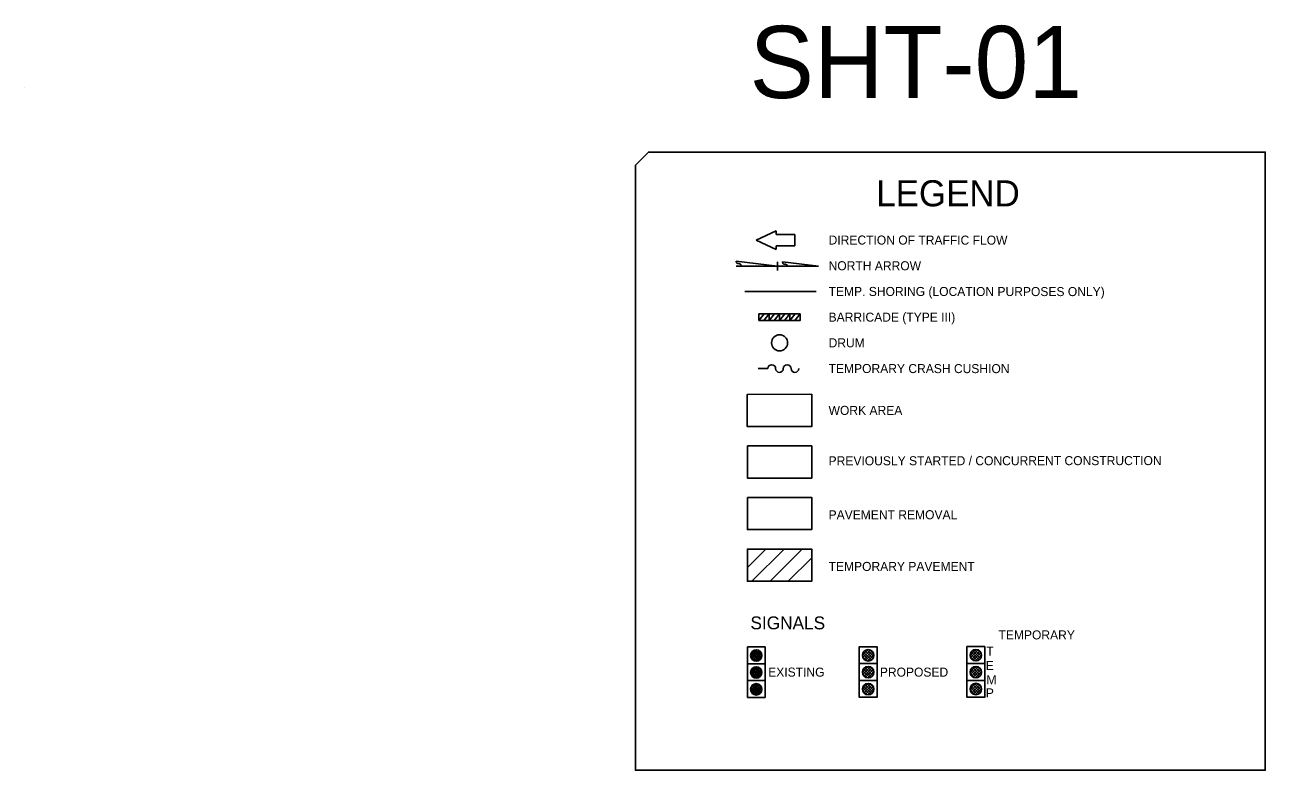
# Model space of a CAD drawing. Extents: x 2486454 to 2490507, y 369321 to 372999.
# Drawn here: x 2487512 to 2488475, y 372420 to 372999 of the extents above; entities that cross this region are included whole.
import ezdxf

# ---------------------------------------------------------------- set-up
doc = ezdxf.new("R2010")
doc.units = 0
for name, color, linetype in [('DEV BORDER CELL', 7, 'Continuous'), ('Scratch_Level_3', 7, 'Continuous'), ('TC CONSTRUCTION PROPOSED ROADWAY SHADE', 7, 'Continuous'), ('TC CONSTRUCTION REMOVAL OF EXIST ASPH PVMT HATCHING', 7, 'Continuous'), ('TC CONSTRUCTION TEMP PAVEMENT FULL DEPTH SHADE', 7, 'Continuous'), ('TC CONSTRUCTION TEMP PAVEMENT HATCHING', 7, 'Continuous'), ('TC CONSTRUCTION TEMP SHORING', 7, 'Continuous'), ('TC DEV ATTENUATOR', 7, 'Continuous'), ('TC DEV BARRICADE', 7, 'Continuous'), ('TC DEV DRUM', 7, 'Continuous'), ('TC DEV SIGNAL', 7, 'Continuous'), ('TC LABEL DIRECTION OF TRAFFIC FLOW ARROW', 7, 'Continuous'), ('TC SHEET BORDER LINE THIN', 7, 'Continuous'), ('TC SHEET LAYOUT SHAPE', 7, 'Continuous'), ('TC SHEET NORTH ARROW', 7, 'Continuous'), ('TC SHEET TEXT', 7, 'Continuous')]:
    doc.layers.add(name, color=color, linetype=linetype)

msp = doc.modelspace()

# ---------------------------------------------------------------- linework, layer by layer
at = {"layer": 'DEV BORDER CELL'}
msp.add_lwpolyline([(2488122.95, 372711.96), (2488072.95, 372711.93), (2488072.96, 372686.93), (2488122.96, 372686.96)], close=True, dxfattribs=at)
at = {"layer": 'Scratch_Level_3'}
msp.add_line((2487512.21, 372950.09), (2487512.21, 372950.09), dxfattribs=at)
at = {"layer": 'TC CONSTRUCTION PROPOSED ROADWAY SHADE'}
msp.add_lwpolyline([(2488072.95, 372711.93), (2488122.95, 372711.96), (2488122.96, 372686.96), (2488072.96, 372686.93)], close=True, dxfattribs=at)
at = {"layer": 'TC CONSTRUCTION REMOVAL OF EXIST ASPH PVMT HATCHING'}
msp.add_lwpolyline([(2488073, 372631.92), (2488123, 372631.95), (2488123.02, 372606.95), (2488073.02, 372606.92)], close=True, dxfattribs=at)
at = {"layer": 'TC CONSTRUCTION TEMP PAVEMENT FULL DEPTH SHADE'}
msp.add_lwpolyline([(2488073.03, 372566.82), (2488123.03, 372566.85), (2488123.02, 372591.85), (2488073.02, 372591.82), (2488073.03, 372566.82)], dxfattribs=at)
at = {"layer": 'TC CONSTRUCTION TEMP PAVEMENT HATCHING'}
for p, q in [((2488073.02, 372591.62), (2488073.21, 372591.82)), ((2488073.03, 372577.49), (2488087.36, 372591.83)), ((2488076.5, 372566.82), (2488101.52, 372591.84)), ((2488090.65, 372566.83), (2488115.67, 372591.85)), ((2488104.8, 372566.84), (2488123.02, 372585.06))]:
    msp.add_line(p, q, dxfattribs=at)
at = {"layer": 'TC CONSTRUCTION TEMP SHORING'}
msp.add_line((2488071.09, 372791.72), (2488126.3, 372791.72), dxfattribs=at)
at = {"layer": 'TC DEV ATTENUATOR'}
msp.add_line((2488081.48, 372731.9), (2488088.91, 372731.9), dxfattribs=at)
for centre, radius, start, end in [((2488091.95, 372731.9), 3.03, 359.99986, 179.99986), ((2488097.95, 372731.9), 2.97, 179.99986, 359.99986), ((2488103.91, 372731.9), 3, 359.99986, 179.99986), ((2488109.95, 372731.9), 2.97, 179.99986, 359.99986)]:
    msp.add_arc(centre, radius, start, end, dxfattribs=at)
at = {"layer": 'TC DEV BARRICADE'}
for p, q in [((2488086.05, 372774.32), (2488082.04, 372769.32)), ((2488082.04, 372769.32), (2488082.04, 372774.32)), ((2488082.04, 372774.32), (2488082.04, 372774.32)), ((2488082.04, 372774.32), (2488086.05, 372774.32)), ((2488090.04, 372774.32), (2488085.79, 372769.33)), ((2488085.79, 372769.33), (2488090.04, 372769.32)), ((2488090.04, 372769.32), (2488090.04, 372774.32)), ((2488090.04, 372774.32), (2488090.04, 372774.32)), ((2488094.05, 372774.32), (2488090.04, 372769.32)), ((2488090.04, 372769.32), (2488090.04, 372774.32)), ((2488090.04, 372774.32), (2488090.04, 372774.32)), ((2488090.04, 372774.32), (2488094.05, 372774.32)), ((2488098.04, 372774.32), (2488093.79, 372769.33)), ((2488093.79, 372769.33), (2488098.04, 372769.32)), ((2488102.05, 372774.32), (2488098.04, 372769.32)), ((2488098.04, 372769.32), (2488098.04, 372774.32)), ((2488098.04, 372774.32), (2488098.04, 372774.32)), ((2488098.04, 372774.32), (2488102.05, 372774.32)), ((2488098.04, 372769.32), (2488098.04, 372774.32)), ((2488098.04, 372774.32), (2488098.04, 372774.32)), ((2488106.04, 372774.32), (2488101.79, 372769.33)), ((2488101.79, 372769.33), (2488106.04, 372769.32)), ((2488110.05, 372774.32), (2488106.04, 372769.32)), ((2488106.04, 372769.32), (2488106.04, 372774.32)), ((2488106.04, 372774.32), (2488106.04, 372774.32)), ((2488106.04, 372774.32), (2488110.05, 372774.32)), ((2488106.04, 372769.32), (2488106.04, 372774.32)), ((2488106.04, 372774.32), (2488106.04, 372774.32)), ((2488114.04, 372774.32), (2488109.79, 372769.33)), ((2488109.79, 372769.33), (2488114.04, 372769.32)), ((2488114.04, 372769.32), (2488114.04, 372774.32)), ((2488114.04, 372774.32), (2488114.04, 372774.32))]:
    msp.add_line(p, q, dxfattribs=at)
for points in [[(2488090.04, 372774.32), (2488085.79, 372769.33), (2488082.04, 372769.32), (2488086.05, 372774.32)], [(2488090.04, 372774.32), (2488090.04, 372769.32), (2488082.04, 372769.32), (2488082.04, 372774.32)], [(2488098.04, 372774.32), (2488093.79, 372769.33), (2488090.04, 372769.32), (2488094.05, 372774.32)], [(2488098.04, 372774.32), (2488098.04, 372769.32), (2488090.04, 372769.32), (2488090.04, 372774.32)], [(2488106.04, 372774.32), (2488101.79, 372769.33), (2488098.04, 372769.32), (2488102.05, 372774.32)], [(2488106.04, 372774.32), (2488106.04, 372769.32), (2488098.04, 372769.32), (2488098.04, 372774.32)], [(2488114.04, 372774.32), (2488109.79, 372769.33), (2488106.04, 372769.32), (2488110.05, 372774.32)], [(2488114.04, 372774.32), (2488114.04, 372769.32), (2488106.04, 372769.32), (2488106.04, 372774.32)]]:
    msp.add_lwpolyline(points, close=True, dxfattribs=at)
at = {"layer": 'TC DEV DRUM'}
msp.add_circle((2488098.04, 372751.92), 6.25, dxfattribs=at)
msp.add_circle((2488098.04, 372751.92), 6.25, dxfattribs=at)
at = {"layer": 'TC DEV SIGNAL'}
for p, q in [((2488073.03, 372515.93), (2488086.83, 372515.93)), ((2488073.03, 372502.83), (2488073.03, 372515.93)), ((2488086.83, 372515.93), (2488086.83, 372502.83)), ((2488075.5, 372509.05), (2488079.75, 372504.8)), ((2488075.51, 372509.55), (2488079.62, 372513.66)), ((2488075.61, 372508.23), (2488080.93, 372513.55)), ((2488075.63, 372510.33), (2488081.03, 372504.93)), ((2488075.99, 372507.2), (2488081.96, 372513.17)), ((2488076.03, 372511.34), (2488082.05, 372505.33)), ((2488076.05, 372507.08), (2488077.78, 372505.35)), ((2488076.25, 372511.7), (2488077.46, 372512.91)), ((2488076.56, 372506.35), (2488082.81, 372512.61)), ((2488076.61, 372512.17), (2488082.88, 372505.91)), ((2488077.29, 372505.67), (2488083.5, 372511.88)), ((2488077.36, 372512.84), (2488083.55, 372506.65)), ((2488078.18, 372505.15), (2488084.01, 372510.98)), ((2488078.27, 372513.34), (2488084.05, 372507.57)), ((2488079.29, 372504.84), (2488084.32, 372509.88)), ((2488079.4, 372513.63), (2488084.34, 372508.69)), ((2488080.72, 372504.86), (2488084.3, 372508.44)), ((2488080.88, 372513.56), (2488084.27, 372510.18)), ((2488162.4, 372509.51), (2488166.7, 372513.81)), ((2488165.9, 372505.06), (2488162.5, 372508.51)), ((2488167.95, 372505.16), (2488162.55, 372510.56)), ((2488162.75, 372507.71), (2488168.5, 372513.51)), ((2488169.4, 372505.86), (2488163.25, 372511.96)), ((2488163.55, 372506.41), (2488169.8, 372512.66)), ((2488170.45, 372506.91), (2488164.3, 372513.06)), ((2488164.75, 372505.51), (2488170.7, 372511.41)), ((2488171.1, 372508.36), (2488165.75, 372513.71)), ((2488166.4, 372505.06), (2488171.2, 372509.81)), ((2488171.05, 372510.51), (2488167.95, 372513.66)), ((2488169.3, 372505.81), (2488170.55, 372507.06)), ((2488245.97, 372509.56), (2488250.27, 372513.86)), ((2488249.47, 372505.11), (2488246.07, 372508.56)), ((2488251.52, 372505.21), (2488246.12, 372510.61)), ((2488246.32, 372507.76), (2488252.07, 372513.56)), ((2488252.97, 372505.91), (2488246.82, 372512.01)), ((2488247.12, 372506.46), (2488253.37, 372512.71)), ((2488254.02, 372506.96), (2488247.87, 372513.11)), ((2488248.32, 372505.56), (2488254.27, 372511.46)), ((2488254.67, 372508.41), (2488249.32, 372513.76)), ((2488249.97, 372505.11), (2488254.77, 372509.86)), ((2488254.62, 372510.56), (2488251.52, 372513.71)), ((2488252.87, 372505.86), (2488254.12, 372507.11)), ((2488073.03, 372502.83), (2488086.83, 372502.83)), ((2488073.03, 372489.73), (2488073.03, 372502.83)), ((2488075.5, 372496.17), (2488079.89, 372500.57)), ((2488075.5, 372496.27), (2488080.07, 372491.69)), ((2488075.66, 372494.92), (2488081.14, 372500.4)), ((2488075.71, 372497.48), (2488081.28, 372491.9)), ((2488075.91, 372498), (2488078.07, 372500.15)), ((2488076.08, 372493.93), (2488082.14, 372499.98)), ((2488076.15, 372498.45), (2488082.25, 372492.34)), ((2488076.68, 372493.11), (2488082.95, 372499.38)), ((2488076.77, 372499.24), (2488083.04, 372492.96)), ((2488077.44, 372492.46), (2488083.6, 372498.62)), ((2488077.55, 372499.87), (2488083.68, 372493.75)), ((2488078.37, 372491.98), (2488084.09, 372497.69)), ((2488078.51, 372500.33), (2488084.14, 372494.7)), ((2488079.52, 372491.71), (2488084.35, 372496.54)), ((2488079.69, 372500.56), (2488084.36, 372495.89)), ((2488081.32, 372500.34), (2488084.15, 372497.52)), ((2488086.83, 372502.83), (2488086.83, 372489.73)), ((2488162.4, 372496.41), (2488166.7, 372500.71)), ((2488167.95, 372492.06), (2488162.55, 372497.46)), ((2488162.75, 372494.61), (2488168.5, 372500.41)), ((2488169.4, 372492.76), (2488163.25, 372498.86)), ((2488163.55, 372493.31), (2488169.8, 372499.56)), ((2488170.45, 372493.81), (2488164.3, 372499.96)), ((2488164.75, 372492.41), (2488170.7, 372498.31)), ((2488171.1, 372495.26), (2488165.75, 372500.61)), ((2488166.4, 372491.96), (2488171.2, 372496.71)), ((2488171.05, 372497.41), (2488167.95, 372500.56)), ((2488245.97, 372496.46), (2488250.27, 372500.76)), ((2488251.52, 372492.11), (2488246.12, 372497.51)), ((2488246.32, 372494.66), (2488252.07, 372500.46)), ((2488252.97, 372492.81), (2488246.82, 372498.91)), ((2488247.12, 372493.36), (2488253.37, 372499.61)), ((2488254.02, 372493.86), (2488247.87, 372500.01)), ((2488248.32, 372492.46), (2488254.27, 372498.36)), ((2488254.67, 372495.31), (2488249.32, 372500.66)), ((2488249.97, 372492.01), (2488254.77, 372496.76)), ((2488254.62, 372497.46), (2488251.52, 372500.61)), ((2488086.83, 372489.73), (2488073.03, 372489.73)), ((2488073.03, 372476.63), (2488073.03, 372489.73)), ((2488075.52, 372483.53), (2488079.43, 372487.44)), ((2488075.58, 372482.17), (2488080.79, 372487.38)), ((2488075.78, 372494.57), (2488078.38, 372491.97)), ((2488075.93, 372481.11), (2488081.85, 372487.03)), ((2488076.48, 372480.24), (2488082.72, 372486.48)), ((2488077.68, 372486.85), (2488083.76, 372480.78)), ((2488078.67, 372487.28), (2488084.19, 372481.76)), ((2488079.9, 372487.47), (2488084.37, 372482.99)), ((2488081.06, 372491.84), (2488084.23, 372495)), ((2488081.66, 372487.12), (2488084.02, 372484.75)), ((2488086.83, 372489.73), (2488086.83, 372476.63)), ((2488162.4, 372483.31), (2488166.7, 372487.61)), ((2488165.9, 372491.96), (2488162.5, 372495.41)), ((2488162.75, 372481.51), (2488168.5, 372487.31)), ((2488163.55, 372480.21), (2488169.8, 372486.46)), ((2488170.45, 372480.71), (2488164.3, 372486.86)), ((2488171.1, 372482.16), (2488165.75, 372487.51)), ((2488171.05, 372484.31), (2488167.95, 372487.46)), ((2488169.3, 372492.71), (2488170.55, 372493.96)), ((2488245.97, 372483.36), (2488250.27, 372487.66)), ((2488249.47, 372492.01), (2488246.07, 372495.46)), ((2488246.32, 372481.56), (2488252.07, 372487.36)), ((2488247.12, 372480.26), (2488253.37, 372486.51)), ((2488254.02, 372480.76), (2488247.87, 372486.91)), ((2488254.67, 372482.21), (2488249.32, 372487.56)), ((2488254.62, 372484.36), (2488251.52, 372487.51)), ((2488252.87, 372492.76), (2488254.12, 372494.01)), ((2488075.51, 372483.37), (2488080.27, 372478.6)), ((2488075.67, 372481.79), (2488078.69, 372478.77)), ((2488075.76, 372484.53), (2488081.44, 372478.85)), ((2488076.23, 372485.47), (2488082.38, 372479.33)), ((2488076.88, 372486.24), (2488083.15, 372479.97)), ((2488077.19, 372479.54), (2488083.42, 372485.77)), ((2488078.07, 372479), (2488083.96, 372484.9)), ((2488079.14, 372478.66), (2488084.3, 372483.82)), ((2488080.52, 372478.63), (2488084.33, 372482.44)), ((2488165.9, 372478.86), (2488162.5, 372482.31)), ((2488167.95, 372478.96), (2488162.55, 372484.36)), ((2488169.4, 372479.66), (2488163.25, 372485.76)), ((2488164.75, 372479.31), (2488170.7, 372485.21)), ((2488166.4, 372478.86), (2488171.2, 372483.61)), ((2488169.3, 372479.61), (2488170.55, 372480.86)), ((2488249.47, 372478.91), (2488246.07, 372482.36)), ((2488251.52, 372479.01), (2488246.12, 372484.41)), ((2488252.97, 372479.71), (2488246.82, 372485.81)), ((2488248.32, 372479.36), (2488254.27, 372485.26)), ((2488249.97, 372478.91), (2488254.77, 372483.66)), ((2488252.87, 372479.66), (2488254.12, 372480.91)), ((2488086.83, 372476.63), (2488073.03, 372476.63))]:
    msp.add_line(p, q, dxfattribs=at)
for points in [[(2488159.9, 372516.11), (2488173.7, 372516.11), (2488173.7, 372476.81), (2488159.9, 372476.81)], [(2488159.9, 372503.01), (2488173.7, 372503.01), (2488173.7, 372516.11), (2488159.9, 372516.11)], [(2488243.47, 372516.16), (2488257.27, 372516.16), (2488257.27, 372476.86), (2488243.47, 372476.86)], [(2488243.47, 372503.06), (2488257.27, 372503.06), (2488257.27, 372516.16), (2488243.47, 372516.16)], [(2488159.9, 372489.91), (2488173.7, 372489.91), (2488173.7, 372503.01), (2488159.9, 372503.01)], [(2488243.47, 372489.96), (2488257.27, 372489.96), (2488257.27, 372503.06), (2488243.47, 372503.06)], [(2488159.9, 372476.81), (2488173.7, 372476.81), (2488173.7, 372489.91), (2488159.9, 372489.91)], [(2488243.47, 372476.86), (2488257.27, 372476.86), (2488257.27, 372489.96), (2488243.47, 372489.96)]]:
    msp.add_lwpolyline(points, close=True, dxfattribs=at)
for centre in [(2488079.93, 372509.23), (2488166.8, 372509.41), (2488250.37, 372509.46), (2488079.93, 372496.13), (2488166.8, 372496.31), (2488250.37, 372496.36), (2488079.93, 372483.03), (2488166.8, 372483.21), (2488250.37, 372483.26)]:
    msp.add_circle(centre, 4.44, dxfattribs=at)
at = {"layer": 'TC LABEL DIRECTION OF TRAFFIC FLOW ARROW'}
for p, q in [((2488095.48, 372838.94), (2488079.97, 372831.63)), ((2488095.48, 372835.98), (2488095.48, 372838.94)), ((2488109.88, 372835.98), (2488095.48, 372835.98)), ((2488109.88, 372827.29), (2488109.88, 372835.98)), ((2488079.97, 372831.63), (2488095.48, 372824.33)), ((2488095.48, 372824.33), (2488095.48, 372827.29)), ((2488095.48, 372827.29), (2488109.88, 372827.29))]:
    msp.add_line(p, q, dxfattribs=at)
at = {"layer": 'TC SHEET BORDER LINE THIN'}
for points in [[(2488072.95, 372711.93), (2488122.95, 372711.96), (2488122.96, 372686.96), (2488072.96, 372686.93)], [(2488073, 372671.9), (2488123, 372671.93), (2488123.02, 372646.93), (2488073.02, 372646.9)], [(2488073, 372631.92), (2488123, 372631.95), (2488123.02, 372606.95), (2488073.02, 372606.92)], [(2488073.02, 372591.82), (2488123.02, 372591.85), (2488123.03, 372566.85), (2488073.03, 372566.82)]]:
    msp.add_lwpolyline(points, close=True, dxfattribs=at)
at = {"layer": 'TC SHEET LAYOUT SHAPE'}
msp.add_lwpolyline([(2487986.17, 372889.87), (2487996.17, 372899.87), (2488474.93, 372899.87), (2488474.93, 372420.25), (2487986.17, 372420.25)], close=True, dxfattribs=at)
at = {"layer": 'TC SHEET NORTH ARROW'}
for p, q in [((2488096.3, 372811.47), (2488064.41, 372815.39)), ((2488096.3, 372814.89), (2488096.3, 372808.06)), ((2488100.35, 372814.89), (2488128.18, 372811.47)), ((2488100.35, 372814.89), (2488128.18, 372811.47)), ((2488064.41, 372811.47), (2488128.18, 372811.47)), ((2488068.18, 372811.49), (2488096.3, 372811.47)), ((2488128.18, 372811.47), (2488103.96, 372811.48)), ((2488128.18, 372811.47), (2488103.96, 372811.48))]:
    msp.add_line(p, q, dxfattribs=at)
for points in [[(2488064.41, 372815.39), (2488064.31, 372813.41), (2488068.21, 372813.34), (2488068.18, 372811.49)], [(2488103.96, 372811.47), (2488104.15, 372812.85), (2488100.25, 372812.91), (2488100.35, 372814.89)], [(2488103.96, 372811.47), (2488104.15, 372812.85), (2488100.25, 372812.91), (2488100.35, 372814.89)]]:
    msp.add_open_spline(points, degree=2, dxfattribs=at)

# ---------------------------------------------------------------- texts
at = {"layer": 'TC DEV SIGNAL'}
for s, p in [('T', (2488258.52, 372509)), ('E', (2488258.04, 372497.94)), ('M', (2488258.59, 372486.9)), ('P', (2488258.11, 372476.72))]:
    msp.add_text(s, height=7, rotation=359.99986, dxfattribs=at).set_placement(p)
at = {"layer": 'TC SHEET LAYOUT SHAPE'}
msp.add_text('SHT-01', height=55.996, rotation=0.00008, dxfattribs=at).set_placement((2488074.73, 372941.87))
at = {"layer": 'TC SHEET TEXT'}
for s, height, rotation, p in [('LEGEND', 20.254, 359.95966, (2488173.06, 372857.86)), ('DIRECTION OF TRAFFIC FLOW', 7, 359.95966, (2488136.07, 372828.19)), ('NORTH ARROW', 7, 359.95966, (2488136.07, 372808.25)), ('TEMP. SHORING (LOCATION PURPOSES ONLY)', 7, 359.95966, (2488136.07, 372788.31)), ('BARRICADE (TYPE III)', 7, 359.95966, (2488136.07, 372768.37)), ('DRUM', 7, 359.95966, (2488136.07, 372748.43)), ('TEMPORARY CRASH CUSHION', 7, 359.95966, (2488136.07, 372728.48)), ('WORK AREA', 7, 0.04028, (2488136.07, 372695.97)), ('PREVIOUSLY STARTED / CONCURRENT CONSTRUCTION', 7, 0.04028, (2488136.07, 372656.84)), ('PAVEMENT REMOVAL', 7, 0.04028, (2488136.07, 372614.95)), ('TEMPORARY PAVEMENT', 7, 0.04028, (2488136.07, 372574.86)), ('SIGNALS', 10, 359.95966, (2488075.41, 372529.59)), ('TEMPORARY ', 7, 359.95966, (2488267.93, 372521.76)), ('EXISTING', 7, 359.95966, (2488089.19, 372492.88)), ('PROPOSED', 7, 359.95966, (2488175.84, 372492.88))]:
    msp.add_text(s, height=height, rotation=rotation, dxfattribs=at).set_placement(p)

doc.saveas('drawing.dxf')
